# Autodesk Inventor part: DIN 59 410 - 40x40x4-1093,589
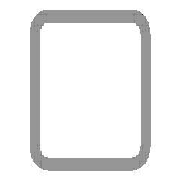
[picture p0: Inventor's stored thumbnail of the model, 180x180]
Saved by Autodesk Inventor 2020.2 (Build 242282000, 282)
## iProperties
Manager: www.cadconsulting.pl
Company: Fabian Stasiak CAD Consulting
IsCustomPart: 1
_CCFamilyMember: 20
_CCFamilyDisplayName: DIN 59410 (Kwadrat) - Rurki stalowe o przekroju kwadratowym formowane na gorąco
_FrameMemberDoc: Frame Member File
_Version: 15.0.0
_GetPNFromCC: 1
Created: 2015-01
Part Number: DIN 59 410 - 40x40x4-1093,589
Material: Stal, miękka
Description: Rurki stalowe o przekroju kwadratowym formowane na gorąco
Document SubType Name: Modellieren
Standard: DIN
Designer: F.Stasiak
Standards Organization: DIN
Language: pl-PL
Size Designation: 40x40x4
Categories: <MemberInstance><Categories><Category DisplayName="Kształtowniki konstrukcyjne" InternalName="089c4875-fa83-4c05-b084-43b9cc11f5ed" Mnemonic="GRDR"><CategoryPar
Stock Number: 40x40x4
Density: 7.85 g/cm^3
Appearance: Częściowo polerowana
Mass: 4423.13 g
Surface Area: 2832.4 cm^2
Volume: 563.456 cm^3
Catalog Web Link: www.expertbooks.pl
G_W: 40,000 mm
G_H: 40,000 mm
+E0E438BC-4BDD-4229-943C-4A83AABB72B9+CUTDETAIL1: Wytnij
+526A10A7-5559-4FE8-89C2-4CFBF069D61E+CUTDETAIL2: Wytnij
G_L: 1093,589 mm
Author: F.Stasiak
Subject: Zbiór ćwiczeń. Autodesk Inventor 2020. Kurs Professional
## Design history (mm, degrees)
node "Płaszczyzna początkowa"
node "Płaszczyzna końcowa"
sketch "Szkic1"
  geometry: L1 (-12, 20)-(12, 20); L2 (20, 12)-(20, -12); L3 (12, -20)-(-12, -20); L4 (-20, -12)-(-20, 12); L5 (-30.32, 0)-(30.32, 0) reference; L6 (0, -30.32)-(0, 30.32) reference; L7 (-12, 16)-(12, 16); L8 (16, 12)-(16, -12); L9 (12, -16)-(-12, -16); L10 (-16, -12)-(-16, 12); A1 r 8 centre (-12, 12) between (-12, 20) and (-20, 12); A2 r 8 centre (12, 12) between (20, 12) and (12, 20); A3 r 8 centre (12, -12) between (12, -20) and (20, -12); A4 r 8 centre (-12, -12) between (-20, -12) and (-12, -20); A5 r 4 centre (-12, 12) between (-12, 16) and (-16, 12); A6 r 4 centre (12, 12) between (16, 12) and (12, 16); A7 r 4 centre (12, -12) between (12, -16) and (16, -12); A8 r 4 centre (-12, -12) between (-16, -12) and (-12, -16); 3 further points
  constraints: 16 end point, 16 point on circle, 8 centre point, 8 tangent, 6 point on line, 4 parallel, 3 equal radius, 3 perpendicular, 1 horizontal, 7 other
  dimensions: "b" = 40 distance of point (-20, 20) point (20, 20); "msp_r" = 8 radius of A1 (= 2 x ParT); "d8" = 20 distance between parallel lines of L4 L6 (= d9); "d9" = 20 distance between parallel lines of L3 L5 (= 0.5 x b); "d10" = 4 distance between parallel lines of L3 L9 (= ParT)
extrude "Bryła" new body sketch "Szkic1" taper "d4" = 0 deg; stored distance "NLG" = 10
node "Driven Length"
  sketch "Sketch2"
    geometry: L1 (0, 0)-(10, 0) reference
    constraints: 2 end point, 1 horizontal
  workplane "Work Plane3"
  sketch "Sketch3"
    geometry: L1 (-2, 22.426)-(12, 22.426) reference; L2 (-2, 1116.016)-(12, 1116.016) reference
    dimensions: "d14" = 1093.5891 distance between parallel lines of L1 L2 (derived)
node "Płaszczyzna konstrukcyjna4"
feature "Podział1"
node "Płaszczyzna konstrukcyjna5"
feature "Podział2"
body "Solid1"
other parameters: "ParT" = 4, "G_OFFSET_START" = -22.42641 [user parameter; used in 1 equation term], "G_OFFSET_END" = -15.35534 [user parameter; used in 1 equation term], "d11" = 22.42641 (= -G_OFFSET_START), "d12" = 1116.01551 (= G_OFFSET_END + B_L), "G_L" = 1093.5891 (= d14) [user parameter], "B_L" = 1131.37085 [user parameter; used in 1 equation term], "d13" = 90 deg
